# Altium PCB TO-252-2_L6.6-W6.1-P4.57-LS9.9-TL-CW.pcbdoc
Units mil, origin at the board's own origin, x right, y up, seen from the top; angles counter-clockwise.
Board outline 942.28 x 764.28 mil, 2 copper layers (Top Layer, Bottom Layer), stack 0 mil thick; 1 components, 0 nets, 3 pads, 0 vias.
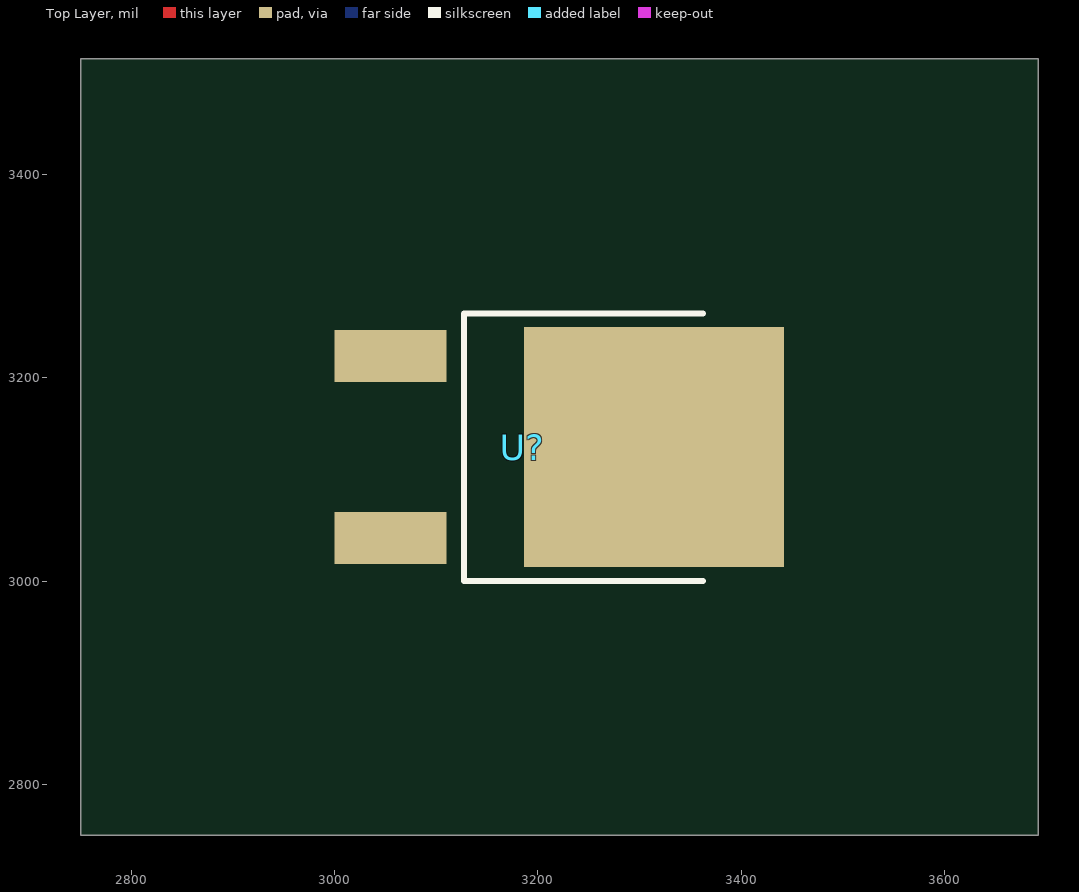
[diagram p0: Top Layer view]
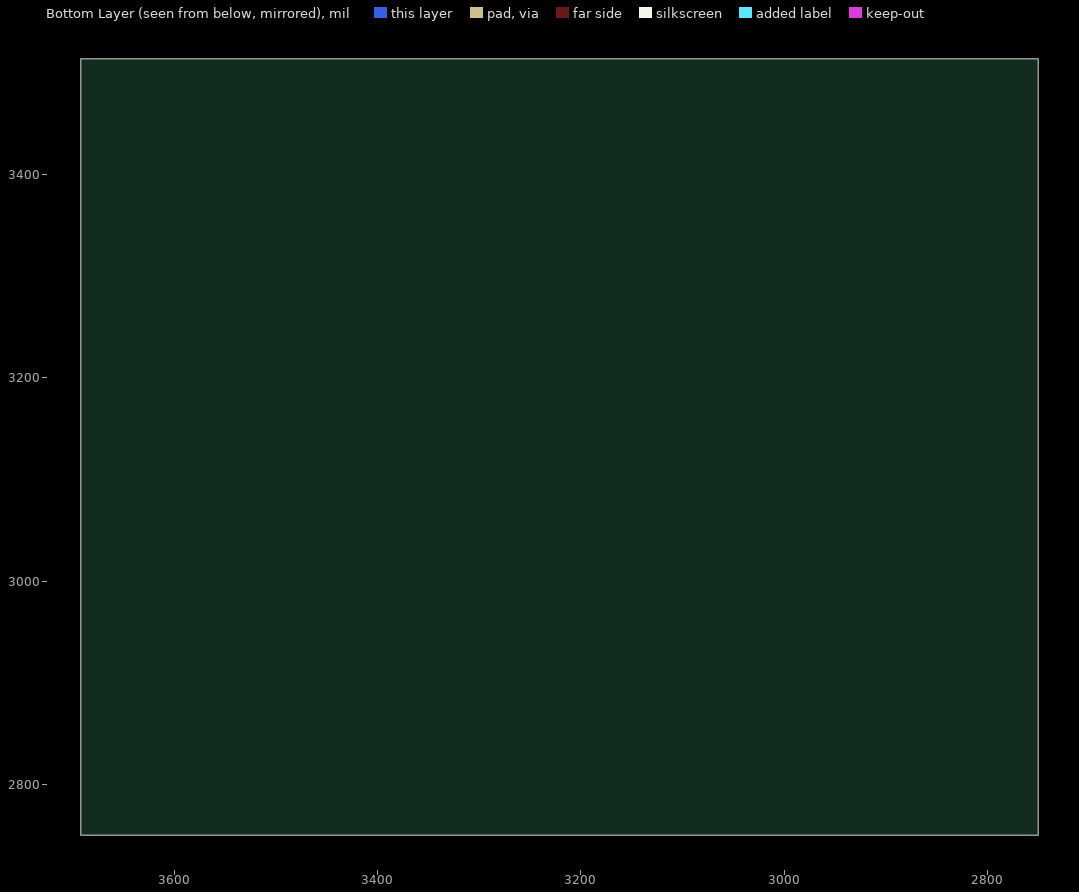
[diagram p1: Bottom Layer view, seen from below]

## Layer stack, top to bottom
Top Layer: signal copper (thickness not stored)
Bottom Layer: signal copper (thickness not stored)

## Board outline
3692.28,2750 2750,2750 2750,3514.28 3692.28,3514.28

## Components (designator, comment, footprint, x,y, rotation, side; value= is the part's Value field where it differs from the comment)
U? "" TO-252-2_L6.6-W6.1-P4.57-LS9.9-TL-CW 3184.72,3132 r0 top

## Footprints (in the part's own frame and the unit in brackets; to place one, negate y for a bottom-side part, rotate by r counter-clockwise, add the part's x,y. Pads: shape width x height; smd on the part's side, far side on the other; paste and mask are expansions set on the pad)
TO-252-2_L6.6-W6.1-P4.57-LS9.9-TL-CW [mm]
  rect 2.8x1.3 smd: 1(-3.292,2.273) 3(-3.292,-2.273)
  rect 6.5x6 smd: 2(3.292,0)
  silkscreen extent -1.46,-3.35 4.51,3.34

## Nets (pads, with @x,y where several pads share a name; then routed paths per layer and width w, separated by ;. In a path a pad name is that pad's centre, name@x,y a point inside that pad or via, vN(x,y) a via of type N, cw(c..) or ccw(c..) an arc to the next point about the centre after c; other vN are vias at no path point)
pads on no net: U?.1 U?.2 U?.3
